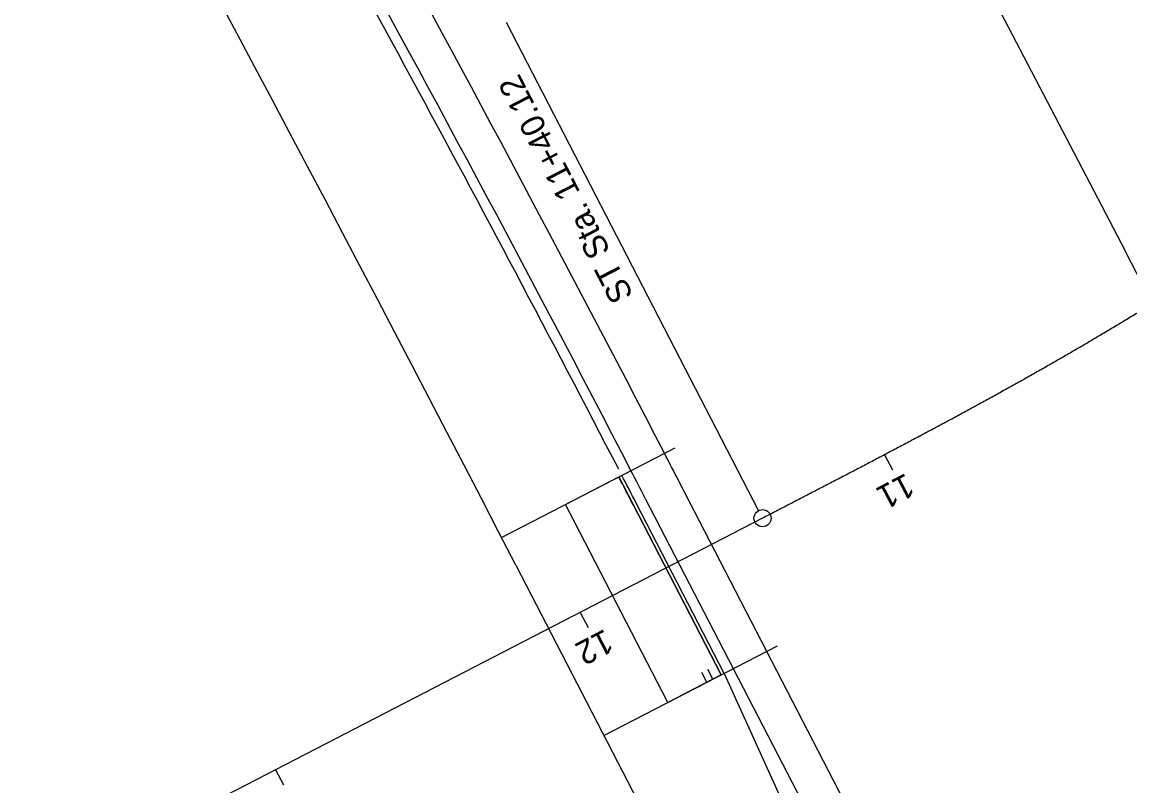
# Model space of a CAD drawing. Extents: x 21904 to 36537, y 12187 to 32963.
# Drawn here: x 24151.9 to 24475, y 28373.6 to 28596.5 of the extents above; entities that cross this region are included whole.
import ezdxf

# ---------------------------------------------------------------- set-up
doc = ezdxf.new("R2010")
doc.units = 0
for name, color, linetype in [('BR_X_Beam_Centerline', 7, 'Continuous'), ('BR_X_Dia_Centerline', 7, 'Continuous'), ('BR_X_Gen_Approach_Slab', 7, 'Continuous'), ('BR_X_Sub_Backwall', 7, 'Continuous'), ('BR_X_Sub_Hidden', 7, 'Continuous'), ('BR_X_Sub_Object', 7, 'Continuous'), ('GE_X_CL_50', 7, 'Continuous'), ('PM_X_Channelizing_Line', 7, 'Continuous')]:
    doc.layers.add(name, color=color, linetype=linetype)

msp = doc.modelspace()

# ---------------------------------------------------------------- linework, layer by layer
at = {"layer": 'BR_X_Beam_Centerline'}
for p, q in [((24291.76, 28446.08), (24342.38, 28472.27)), ((24321.6, 28388.33), (24372.24, 28414.49))]:
    msp.add_line(p, q, dxfattribs=at)
at = {"layer": 'BR_X_Dia_Centerline'}
msp.add_line((24295.92, 28438.03), (26722.77, 23740.28), dxfattribs=at)
msp.add_arc((11569.81, 21863.73), 14323.94, 27.320833, 30.120833, dxfattribs=at)
at = {"layer": 'BR_X_Gen_Approach_Slab'}
for p, q in [((24353.36, 28404.76), (24351.89, 28407.6)), ((24355.35, 28405.78), (24349.66, 28402.85)), ((24351.65, 28403.87), (24350.19, 28406.72)), ((24352.51, 28404.31), (24352.51, 28404.31)), ((24352.51, 28404.31), (24352.51, 28404.31))]:
    msp.add_line(p, q, dxfattribs=at)
msp.add_arc((18135.2, 25260.67), 6971.31, 27.373526, 29.496041, dxfattribs=at)
at = {"layer": 'BR_X_Sub_Backwall'}
for q in [(24331.02, 28456.16), (24427.16, 28251.52)]:
    msp.add_line((24356.69, 28406.46), q, dxfattribs=at)
msp.add_arc((11569.81, 21863.73), 14363.44, 27.320833, 27.357089, dxfattribs=at)
at = {"layer": 'BR_X_Sub_Hidden'}
for p, q in [((24310.41, 28455.73), (24325.95, 28463.77)), ((24355.8, 28406), (24330.13, 28455.7)), ((24340.25, 28397.97), (24314.58, 28447.66)), ((24340.25, 28397.97), (24355.8, 28406))]:
    msp.add_line(p, q, dxfattribs=at)
msp.add_lwpolyline([(24325.95, 28463.77), (24330.13, 28455.7), (24355.8, 28406), (24340.25, 28397.97), (24314.58, 28447.66), (24310.41, 28455.73)], close=True, dxfattribs=at)
for centre, end in [((11578.69, 21868.32), 27.357114), ((11563.14, 21860.29), 27.35707)]:
    msp.add_arc(centre, 14352.44, 27.320833, end, dxfattribs=at)
at = {"layer": 'BR_X_Sub_Object'}
for p, q in [((24800.56, 27577.74), (24343.45, 28462.58)), ((24333.68, 28457.53), (24790.79, 27572.69))]:
    msp.add_line(p, q, dxfattribs=at)
for centre, radius, start, end in [((17498.11, 24931.04), 7702.63, 27.35709, 30.231556), ((18135.2, 25260.67), 6974.31, 27.357089, 30.529372), ((11569.81, 21863.73), 14377.44, 27.320833, 27.35709), ((11569.81, 21863.73), 14366.44, 27.320833, 27.357089)]:
    msp.add_arc(centre, radius, start, end, dxfattribs=at)
at = {"layer": 'GE_X_CL_50'}
for p, q in [((24366.73, 28453.96), (24293.18, 28596.34)), ((24403.48, 28470.25), (24405.81, 28465.82)), ((24367.88, 28451.74), (23024.38, 27757.69)), ((24314.68, 28424.26), (24316.98, 28419.82)), ((24225.84, 28378.36), (24228.13, 28373.92))]:
    msp.add_line(p, q, dxfattribs=at)
msp.add_circle((24367.88, 28451.74), 2.5, dxfattribs=at)
msp.add_spline([(24498.6, 28525.16), (24496.9, 28524.05), (24495.2, 28522.94), (24493.5, 28521.84), (24491.8, 28520.74), (24490.09, 28519.65), (24488.38, 28518.56), (24486.67, 28517.48), (24484.95, 28516.4), (24483.23, 28515.33), (24481.51, 28514.26), (24479.79, 28513.19), (24478.06, 28512.13), (24476.33, 28511.07), (24474.6, 28510.02), (24472.87, 28508.97), (24471.13, 28507.92), (24469.39, 28506.88), (24467.65, 28505.84), (24465.91, 28504.8), (24464.16, 28503.77), (24462.42, 28502.75), (24460.67, 28501.72), (24458.91, 28500.7), (24457.16, 28499.68), (24455.41, 28498.67), (24453.65, 28497.66), (24451.89, 28496.65), (24450.13, 28495.65), (24448.37, 28494.65), (24446.6, 28493.65), (24444.84, 28492.65), (24443.07, 28491.66), (24441.3, 28490.67), (24439.53, 28489.69), (24437.76, 28488.7), (24435.98, 28487.72), (24434.21, 28486.74), (24432.43, 28485.77), (24430.65, 28484.79), (24428.87, 28483.82), (24427.09, 28482.85), (24425.31, 28481.89), (24423.53, 28480.92), (24421.74, 28479.96), (24419.96, 28479), (24418.17, 28478.04), (24416.38, 28477.09), (24414.6, 28476.13), (24412.81, 28475.18), (24411.02, 28474.23), (24409.23, 28473.28), (24407.43, 28472.33), (24405.64, 28471.39), (24403.85, 28470.44), (24402.05, 28469.5), (24400.26, 28468.56), (24398.46, 28467.61), (24396.67, 28466.67), (24394.87, 28465.74), (24393.07, 28464.8), (24391.28, 28463.86), (24389.48, 28462.93), (24387.68, 28461.99), (24385.88, 28461.06), (24384.08, 28460.12), (24382.28, 28459.19), (24380.48, 28458.26), (24378.68, 28457.33), (24376.88, 28456.4), (24375.08, 28455.46), (24373.28, 28454.53), (24371.48, 28453.6), (24369.68, 28452.67), (24367.88, 28451.74)], degree=3, dxfattribs=at)
at = {"layer": 'PM_X_Channelizing_Line'}
msp.add_lwpolyline([(23980.16, 28606.79), (24026.93, 28519.99), (24073.1, 28432.86), (24118.23, 28346.23), (24118.66, 28345.4), (24164.56, 28256.55), (24210.46, 28167.71), (24256.35, 28078.86), (24611.73, 28262.45), (24565.84, 28351.3), (24519.94, 28440.14), (24474.04, 28528.99), (24473.61, 28529.82), (24427.2, 28618.9), (24379.73, 28708.5), (24331.63, 28797.76)], dxfattribs=at)

# ---------------------------------------------------------------- texts
at = {"layer": 'GE_X_CL_50'}
for s, rotation, p in [('ST Sta. 11+40.12', 117.3208, (24330.34, 28516.77)), ('11', 207.7501, (24409.72, 28465.06)), ('12', 207.3208, (24321.92, 28419.56))]:
    msp.add_text(s, height=7, rotation=rotation, dxfattribs=at).set_placement(p)

doc.saveas('drawing.dxf')
